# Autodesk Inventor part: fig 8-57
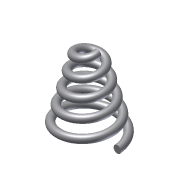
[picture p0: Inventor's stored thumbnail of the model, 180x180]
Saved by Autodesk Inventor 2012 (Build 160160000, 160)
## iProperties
Shininess: 77.0
Length Units: 11269
Angle Units: 11279
Time Units: 11290
Mass Units: 11283
Length Display Precision: 3
Angle Display Precision: 2
Created: 2002-01
Part Number: fig 8-57
Document SubType Name: Modeling
Designer: CADSoft
Density: 1 g/cm^3
Material: Default
Density: 0.0
Volumn: 0.0
Area: 0.0
PropertySet Name: Model Information
Control State: 0
Master: False
Checked Out: False
Author: CADSoft
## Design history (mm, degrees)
sketch "Sketch2"
  geometry: C1 r 2.5 at (-19.895, -0.092)
  constraints: 1 centre point
  dimensions: "d0" = 5 diameter of C1
coil "Coil5" sketch "Sketch2" pitch "d35" = 10; turns "d37" = 5; dims "d36" = 10, "d38" = -15 deg, angle "d39" = 90 deg, angle "d40" = 90 deg, "d41" = 0, "d42" = 0
body "Solid1"
